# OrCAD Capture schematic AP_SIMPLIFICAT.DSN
size A; title: Amplificator audio de putere - Schema de circuit simulata; rev: 1; note: PROIECT P1 - Coca Alin Petru, grupa 432A
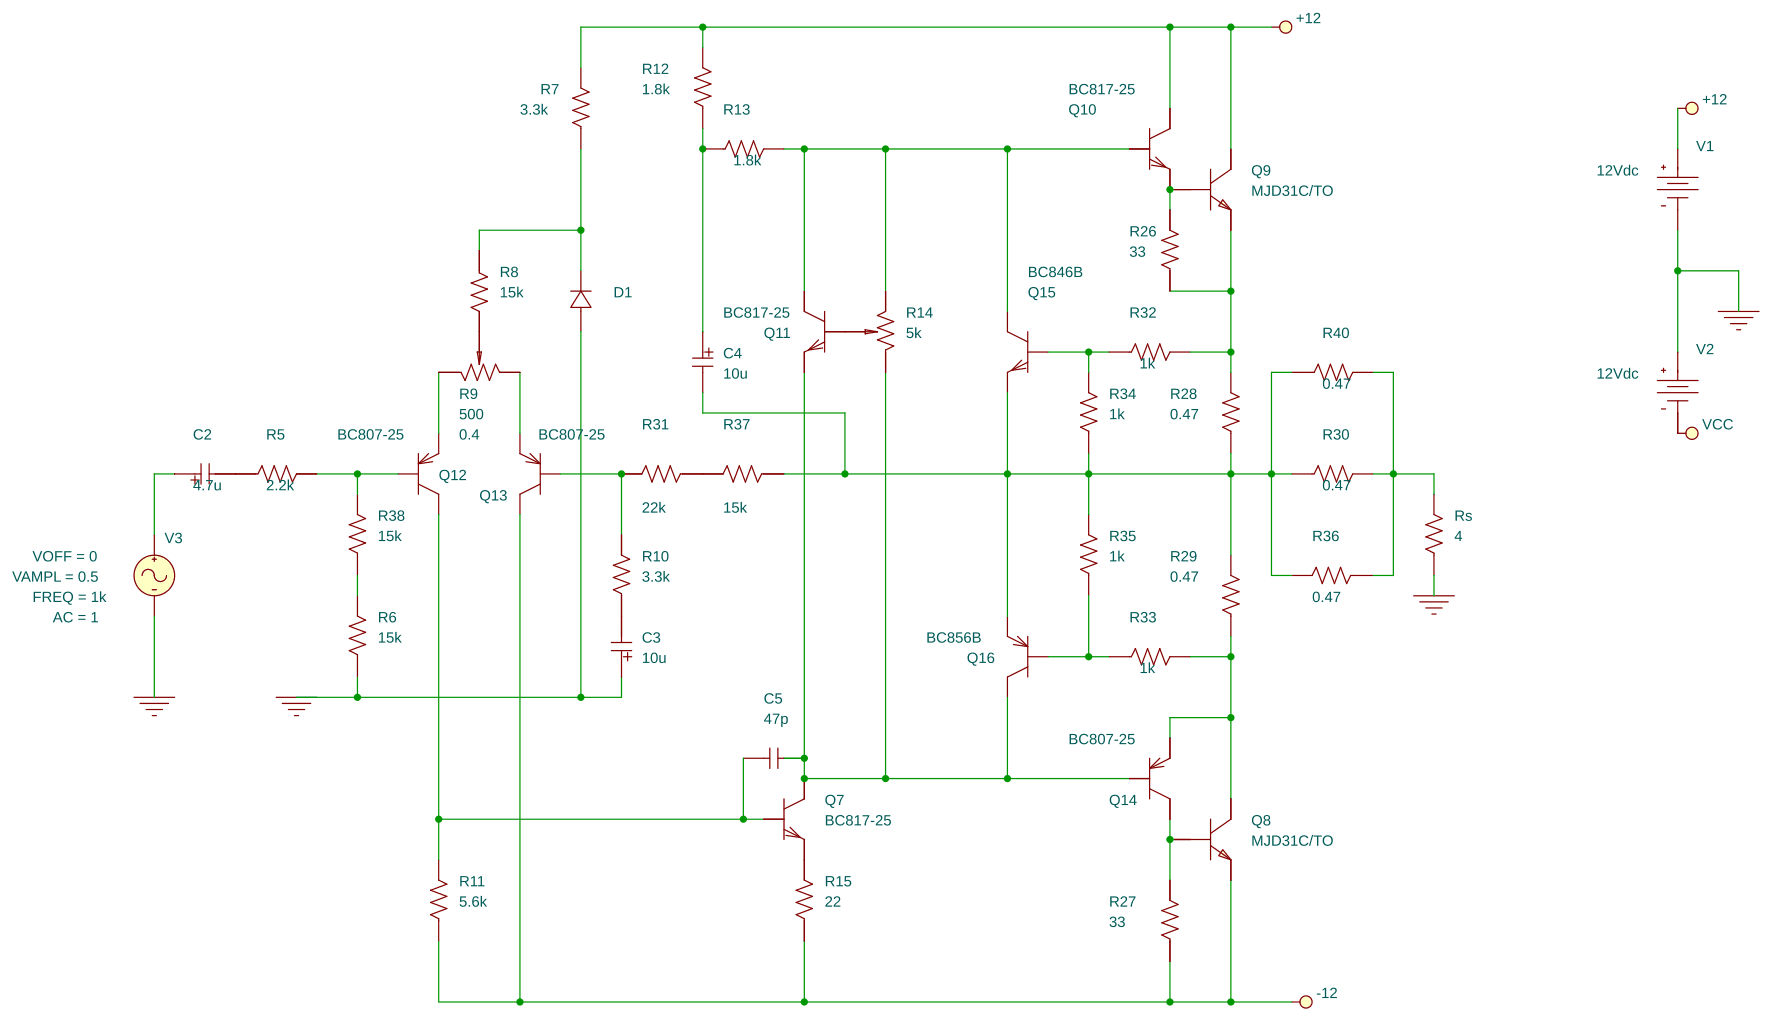
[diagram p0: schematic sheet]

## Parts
C2  4.7u  [PLP3970SMD/AA]
C3  10u  [PLP3970SMD/AA]
C4  10u  [PLP3970SMD/AA]
C5  47p  [cap196]
D1  BZX84C8V2/PLP
Q7  BC817-25  [sot23]
Q8  MJD31C/TO
Q9  MJD31C/TO
Q10  BC817-25  [sot23]
Q11  BC817-25  [sot23]
Q12  BC807-25  [sot23]
Q13  BC807-25  [sot23]
Q14  BC807-25  [sot23]
Q15  BC846B  [sot23]
Q16  BC856B  [sot23]
R5  2.2k  [RC05]
R6  15k  [RC05]
R7  3.3k  [RC05]
R8  15k  [RC05]
R9  500
R10  3.3k  [RC05]
R11  5.6k  [RC05]
R12  1.8k  [RC05]
R13  1.8k  [RC05]
R14  5k
R15  22  [RC05]
R26  33  [RC05]
R27  33  [RC05]
R28  0.47  [RC05]
R29  0.47  [RC05]
R30  0.47  [RC05]
R31  22k  [RC05]
R32  1k  [AXRC05]
R33  1k  [AXRC05]
R34  1k  [AXRC05]
R35  1k  [AXRC05]
R36  0.47  [RC05]
R37  15k  [RC05]
R38  15k  [RC05]
R40  0.47  [RC05]
Rs  4  [RC05]
V1  VDC
V2  VDC
V3  VSIN

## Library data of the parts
C2-C4 = C_elect
C5 = C
D1 = BZX84C8V2_PLP
Q7 Q10 Q11 = BC817-25
Q8 = MJD31C_TO_1
Q9 = MJD31C_TO_3
Q12-Q14 = BC807-25
Q15 = BC846B
Q16 = BC856B
R5-R8 R10-R13 R15 R26-R38 R40 Rs = R
R9 = POT: SET: 0.4
R14 = POT: SET: 0.72
V1 V2 = VDC: DC: 12Vdc
V3 = VSIN: AC: 1; FREQ: 1k; VAMPL: 0.5; VOFF: 0

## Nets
0: C3.1(+) D1.0(1) R6.1 Rs.1 V1.1(-) V2.0(+) V3.2(-)
+12: Q9.3(c) Q10.3(c) R7.2 R12.2 V1.0(+)
-12: Q8.1(e) Q13.3(c) R11.1 R15.1 R27.1 V2.1(-)
N08521: D1.1(2) R7.1 R8.1
N08525: C4.1(+) R12.1 R13.1
N08531: Q10.1(b) Q11.3(c) Q15.3(c) R13.2 R14.3(2)
N08605: Q9.1(e) R26.1 R28.2 R32.2
N08807: Q15.1(b) R32.1 R34.2
N08827: Q12.2(e) R9.1
N08833: Q13.2(e) R9.3(2)
N08855: C5.2 Q7.3(c) Q11.2(e) Q14.1(b) Q16.3(c) R14.1
N08889: C4.2(-) Q15.2(e) Q16.2(e) R28.1 R29.2 R30.1 R34.1 R35.2 R36.2 R37.1 R40.1
N09071: C2.1(+) V3.1(+)
N09087: Q12.1(b) R5.2 R38.2
N09183: C5.1 Q7.1(b) Q12.3(c) R11.2
N09313: Q16.1(b) R33.1 R35.1
N09405: Q8.3(c) Q14.2(e) R29.1 R33.2
N11982: R30.2 R36.1 R40.2 Rs.2
N12314: R6.2 R38.1
N12845: Q13.1(b) R10.2 R31.2
N14439: Q8.2(b) Q14.3(c) R27.2
N33243: Q9.2(b) Q10.2(e) R26.2
N37207: C2.2(-) R5.1
N37208: R8.2 R9.2(t)
N37209: Q7.2(e) R15.2
N37210: Q11.1(b) R14.2(t)
N37211: C3.2(-) R10.1
N37212: R31.1 R37.2
